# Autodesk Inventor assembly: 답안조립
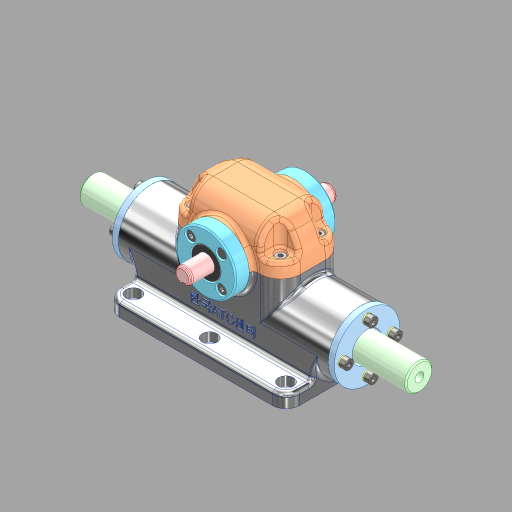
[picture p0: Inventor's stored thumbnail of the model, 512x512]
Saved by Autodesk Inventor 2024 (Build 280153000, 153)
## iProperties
Created: 2024-06
Part Number: 답안조립
Document SubType Name: Assembly
Designer: kh_501
Author: kh_501
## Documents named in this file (13)
- C:\Users\kh_501\Desktop\740604V1006\답안조립.iam
- C:\Users\kh_501\Desktop\740604V1006\본체.ipt
- C:\Users\kh_501\Desktop\740604V1006\깊은 홈 볼 베어링 6901\깊은 홈 볼 베어링 6901.ipt
- C:\Users\kh_501\Desktop\740604V1006\랙\랙.ipt
- C:\Users\kh_501\Desktop\740604V1006\베어링 커버\베어링 커버.ipt
- C:\Users\kh_501\Desktop\740604V1006\부시 커버\부시 커버.ipt
- C:\Users\kh_501\Desktop\740604V1006\스프링 와셔 M4\스프링 와셔 M4.ipt
- C:\Users\kh_501\Desktop\740604V1006\오일레스 부시\오일레스 부시.ipt
- C:\Users\kh_501\Desktop\740604V1006\오일실 12 22 7\오일실 12 22 7.ipt
- C:\Users\kh_501\Desktop\740604V1006\윗커버\윗커버.ipt
- C:\Users\kh_501\Desktop\740604V1006\육각 소켓 머리 볼트 M4x10\육각 소켓 머리 볼트 M4x10.ipt
- C:\Users\kh_501\Desktop\740604V1006\칼라\칼라.ipt
- C:\Users\kh_501\Desktop\740604V1006\피니언\피니언.ipt
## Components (1 placed, 1 different names)
1. 피니언:1
